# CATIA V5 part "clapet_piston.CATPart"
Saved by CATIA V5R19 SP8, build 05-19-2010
Part number: clapet_piston
Revision: ANY
Definition: UNKNOWN
Nomenclature: 22
Source: Unknown
Bounding box of the stored display mesh (mm): x -7 to 7, y -7 to 7, z 0 to 0.5
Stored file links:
  D:\Documents\1_Travail\2- 2I2D\1 - Cours et TD\2- TD\3-TD Assemblage\Pompe AirMan\clapet_piston.CATPart
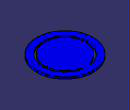
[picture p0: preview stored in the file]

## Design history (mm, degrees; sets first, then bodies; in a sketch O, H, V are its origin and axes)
Body1 "Enlèv. mat.-Extru.1" (main body)
  Solid1: solid without history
